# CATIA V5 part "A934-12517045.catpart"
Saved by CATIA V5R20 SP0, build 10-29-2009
Part number: A934-12517045
Source: Unknown
Property "A": "85.000"
Property "ARTICLENO": "A934-12517045"
Property "B": "20.000"
Property "BOMINFO": "A934-12517045"
Property "CODE": "A934-12517045"
Property "L": "170.000"
Property "L1": "143.370"
Property "LINA": "A934-12517045"
Property "NB": "A934-12517045"
Property "NBSYN": "$CODE."
Property "NN": "A934"
Property "NT": "VDI 3357 H-Type Cam Drivers, self-lubricating"
Property "SUPPLIER": "CF"
Property "T": "45.000"
Property "W": "125.000"
Bounding box of the stored display mesh (mm): x 0 to 170, y 0 to 45, z -125 to 0
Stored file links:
  C:\Users\Utente\Desktop\3D files A934\A934-12517045.catpart
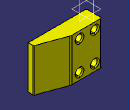
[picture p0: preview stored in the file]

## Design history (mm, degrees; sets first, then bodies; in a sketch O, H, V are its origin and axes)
Body1 "Geometry.1" (main body)
  Solid1 "A934-12517045.catpart": solid without history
